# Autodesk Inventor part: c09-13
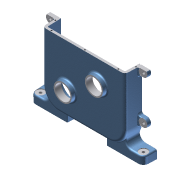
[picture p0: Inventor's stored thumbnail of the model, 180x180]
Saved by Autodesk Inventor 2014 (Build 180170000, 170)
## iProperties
Created: 2008-05
Part Number: c09-13
Document SubType Name: Modeling
Designer: Thom Tremblay
Density: 2.71 g/cm^3
Material: Aluminum 6061
Mass: 2342.12 g
Surface Area: 1959.94 cm^2
Volume: 864.251 cm^3
Appearance: Machined - Aluminum
Author: Thom Tremblay
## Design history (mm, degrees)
derived "c09-12.ipt"
workplane "Work Plane5"
split "Split4"
workplane "Work Plane1"
split "Split1"
workplane "Work Plane2"
split "Split2"
workplane "Work Plane3"
split "Split3"
sketch "Sketch2"
  geometry: L1 (-44.851, 195.566)-(-44.851, 43.154); L2 (0.081, -1.778)-(152.506, -1.778); L3 (197.438, 43.154)-(197.438, 195.566); L4 (-48.026, 195.566)-(-48.026, 43.154); L5 (0.081, -4.953)-(152.506, -4.953); L6 (200.613, 43.154)-(200.613, 195.566); L7 (197.438, 195.566)-(200.613, 195.566); L8 (-48.026, 195.566)-(-44.851, 195.566); L9 (-50.566, 76.123)-(-50.566, 167.659) reference; A1 r 44.932 centre (0.081, 43.154) between (-44.851, 43.154) and (0.081, -1.778); A2 r 48.107 centre (0.081, 43.154) between (-48.026, 43.154) and (0.081, -4.953); A3 r 44.932 centre (152.506, 43.154) between (152.506, -1.778) and (197.438, 43.154); A4 r 48.107 centre (152.506, 43.154) between (152.506, -4.953) and (200.613, 43.154)
  constraints: 16 end point, 8 point on circle, 8 tangent, 4 centre point, 1 collinear, 1 perpendicular
  dimensions: "d87" = 3.175 distance of L4.start L1.start; "d98" = 2.54 distance between parallel lines of L9 L4
extrude "Extrusion1" cut sketch "Sketch2" distance "d7" = 1.5875; taper "d8" = 0 deg
fillet "Fillet1" dims "d9" = 1.27
sketch "Sketch3"
  geometry: A1 r 12.342 centre (0, 9.804) between (-9.709, 17.424) and (0, -2.538) reference; A2 r 12.342 centre (0, -122.307) between (0, -109.965) and (0, -134.649) reference; A3 r 12.342 centre (99.06, -195.936) between (102.192, -207.874) and (111.402, -195.936) reference; A4 r 12.342 centre (185.42, -195.936) between (173.078, -195.936) and (182.288, -207.874) reference; A5 r 12.342 centre (284.48, -122.307) between (284.48, -134.649) and (284.48, -109.965) reference; A6 r 12.342 centre (284.48, 9.804) between (284.48, -2.538) and (294.189, 17.424) reference
hole "Hole4" sketch "Sketch3" at (0, 9.804), (0, -122.307), (99.06, -195.936), (185.42, -195.936), (284.48, -122.307), (284.48, 9.804) diameter "d37" = 8.4328; stored, may be unused: countersink angle "d41" = 82 deg, drill point angle "d43" = 118 deg; dims "d38" = 12.7, "d39" = 25.4, "d40" = 1.5875, "d42" = 19.05
sketch "Sketch4"
  geometry: L1 (-190.442, -18.372)-(-183.68, -30.3) reference; L2 (-255.6, 96.553)-(-248.837, 84.625) reference; L3 (-96.099, 8.151)-(-76.621, 8.151) reference; L4 (9.739, 8.151)-(-9.739, 8.151) reference; A1 r 12.7 centre (0, 0) between (9.739, 8.151) and (-9.739, 8.151) reference; A2 r 12.7 centre (-86.36, 0) between (-76.621, 8.151) and (-96.099, 8.151) reference; A3 r 12.7 centre (-196.361, -29.609) between (-183.68, -30.3) and (-190.442, -18.372) reference; A4 r 12.7 centre (-261.518, 85.317) between (-248.837, 84.625) and (-255.6, 96.553) reference
extrude "Extrusion2" cut sketch "Sketch4" stored distance "d44" = 1.5875; taper "d45" = 0 deg
workplane "Work Plane4"
hole "Hole5" diameter "d49" = 8.4328; stored, may be unused: countersink angle "d53" = 82 deg, drill point angle "d55" = 118 deg; dims "d47" = 25.4, "d48" = 25.4, "d50" = 12.7, "d51" = 25.4, "d52" = 1.5875, "d54" = 19.05
sketch "Sketch5"
  geometry: L1 (7.378, 0)-(0, 0) reference; A1 r 12.7 centre (0, -10.337) between (-12.382, -13.16) and (7.378, 0) reference; 2 further points; 1 other entity
  constraints: 2 other
extrude "Extrusion3" cut sketch "Sketch5" stored distance "d56" = 1.5875; taper "d57" = 0 deg
mirror "Mirror1"
hole "Hole6" diameter "d75" = 47; stored, may be unused: countersink angle "d79" = 82 deg, drill point angle "d81" = 118 deg; dims "d73" = 25.4, "d74" = 25.4, "d76" = 12.7, "d77" = 16.129, "d78" = 7.9502, "d80" = 19.05
chamfer "Chamfer2" distance "d82" = 1.27; stored, may be unused: second distance "d83" = 3.175, angle "d84" = 45 deg
sketch "Sketch7"
  geometry: L1 (233.368, 2.451)-(234.764, 42.445) reference; L2 (0, 0)-(230.829, 0) reference; L3 (-3.935, 42.445)-(-2.538, 2.451) reference; L4 (239.032, 55.493)-(237.175, 2.318); L5 (230.829, -3.81)-(0, -3.81); L6 (-6.346, 2.318)-(-8.203, 55.493); A1 r 2.54 centre (230.829, 2.54) between (230.829, 0) and (233.368, 2.451) reference; A2 r 2.54 centre (0, 2.54) between (-2.538, 2.451) and (0, 0) reference; A3 r 6.35 centre (230.829, 2.54) between (230.829, -3.81) and (237.175, 2.318); A4 r 6.35 centre (0, 2.54) between (-6.346, 2.318) and (0, -3.81); 7 further points
  constraints: 6 end point, 4 point on circle, 3 midpoint, 2 centre point, 2 point on line, 4 other
  dimensions: "d88" = 3.81 distance between parallel lines of L2 L5; "d89" = 101.6 distance of point (115.415, -3.81) point (217.015, -3.81); "d90" = 101.6 distance of point (13.815, -3.81) point (115.415, -3.81) (= d89)
hole "Hole8" sketch "Sketch7" at (115.415, -3.81), (217.015, -3.81), (13.815, -3.81), (-7.275, 28.906), (238.104, 28.906) diameter "d91" = 4.3434; stored, may be unused: countersink angle "d95" = 82 deg, drill point angle "d97" = 118 deg; dims "d92" = 8.89, "d93" = 16.129, "d94" = 7.9502, "d96" = 12.7
body "Solid1"
hole "Hole7" diameter "d66" = 47 (= d75); stored, may be unused: countersink angle "d70" = 82 deg, drill point angle "d72" = 118 deg; dims "d64" = 25.4, "d65" = 25.4, "d67" = 12.7, "d68" = 16.129, "d69" = 7.9502, "d71" = 19.05
tag "TaggingFeature2"
node "Projected Loop1"
node "Projected Loop2"
node "Projected Loop3"
node "Projected Loop4"
node "Projected Loop5"
feature "Solid1::c09-12.ipt" dims "d0" = 10
other parameters: "d1" = 203.2, "d46" = -22.098, "d85" = 0.254, "d99" = -63.5
